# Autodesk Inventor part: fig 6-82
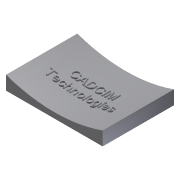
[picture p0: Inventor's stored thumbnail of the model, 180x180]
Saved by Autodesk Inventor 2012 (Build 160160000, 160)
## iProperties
Shininess: 64.0
Length Units: 11269
Angle Units: 11279
Time Units: 11290
Mass Units: 11283
Length Display Precision: 3
Angle Display Precision: 2
Compacted: True
Part Number: fig 6-82
Document SubType Name: Modeling
Created: 2002-12
Designer: deepak
Density: 1 g/cm^3
Material: Default
Density: 0.0
Volumn: 0.0
Area: 0.0
PropertySet Name: Model Information
Control State: 0
Master: False
Checked Out: False
Author: deepak
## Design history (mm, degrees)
sketch "Sketch1"
  geometry: L1 (-39.922, 33.786)-(30.103, 33.786); L2 (30.103, 33.786)-(30.103, -17.894); L3 (30.103, -17.894)-(-39.922, -17.894); L4 (-39.922, -17.894)-(-39.922, 33.786)
  constraints: 8 end point, 2 parallel, 1 horizontal, 1 perpendicular
extrude "Extrusion1" new body sketch "Sketch1" distance "d0" = 10; taper "d1" = 0 deg
workplane "Work Plane1"
sketch "Sketch2"
  geometry: L1 (-37.656, 15.034)-(26.28, 15.034); L2 (26.28, 15.034)-(26.28, 10.168); L3 (26.28, 10.168)-(-37.656, 10.168); L4 (-37.656, 10.168)-(-37.656, 15.034)
  constraints: 2 other
sketch "Sketch3"
  geometry: L1 (70.026, 10)-(0, 10) reference; A1 r 105 centre (35.013, 108.99) between (0, 10) and (70.026, 10)
  constraints: 2 point on circle, 1 centre point
  dimensions: "d5" = 105 radius of A1
extrude "Extrusion2" cut sketch "Sketch3" stored distance "d3" = 10; taper "d4" = 0 deg
emboss "Emboss4" sketch "Sketch2" dims "d14" = 1, "d15" = 0
body "Solid1"
other parameters: "d2" = 5
